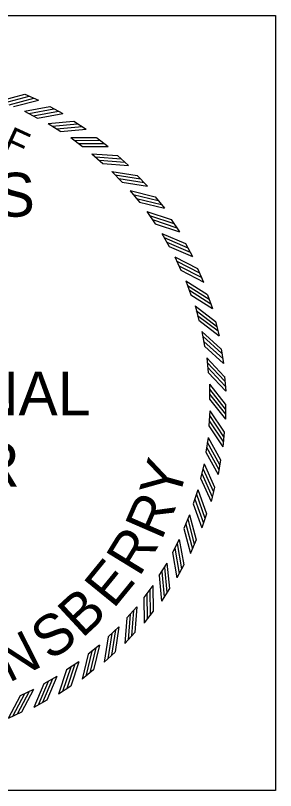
# Model space of a CAD drawing. Extents: x 166 to 3406, y 71 to 2074.
# Drawn here: x 3217.3 to 3309.8, y 386.2 to 662.3 of the extents above; entities that cross this region are included whole.
import ezdxf

# ---------------------------------------------------------------- set-up
doc = ezdxf.new("R2010")
doc.units = 0
doc.layers.add('R_No Plot', color=7, linetype='Continuous')
doc.layers.add('STAMP', color=7, linetype='Continuous')

msp = doc.modelspace()

# ---------------------------------------------------------------- linework, layer by layer
at = {"layer": 'R_No Plot'}
msp.add_lwpolyline([(3033.61, 662.33), (3309.76, 662.33), (3309.76, 386.19), (3033.61, 386.19)], close=True, dxfattribs=at)
at = {"layer": 'STAMP'}
for p, q in [((3220.55, 634.26), (3225.39, 632.19)), ((3229.45, 629.85), (3234.11, 627.38)), ((3220.47, 628.26), (3225.14, 625.78)), ((3237.96, 624.72), (3242.4, 621.88)), ((3228.88, 623.87), (3233.33, 621.02)), ((3236.9, 618.81), (3241.1, 615.6)), ((3246.02, 618.9), (3250.21, 615.7)), ((3244.47, 613.1), (3248.39, 609.56)), ((3253.57, 612.44), (3257.48, 608.91)), ((3251.55, 606.79), (3255.16, 602.94)), ((3260.56, 605.38), (3264.17, 601.53)), ((3258.08, 599.91), (3261.36, 595.77)), ((3266.94, 597.76), (3270.22, 593.63)), ((3264.02, 592.52), (3266.95, 588.13)), ((3272.68, 589.65), (3275.6, 585.26)), ((3269.33, 584.67), (3271.89, 580.04)), ((3277.72, 581.09), (3280.27, 576.47)), ((3273.97, 576.4), (3276.14, 571.58)), ((3282.04, 572.14), (3284.2, 567.33)), ((3277.92, 567.77), (3279.68, 562.79)), ((3285.6, 562.86), (3287.36, 557.89)), ((3281.14, 558.85), (3282.48, 553.74)), ((3288.39, 553.32), (3289.73, 548.22)), ((3283.61, 549.7), (3284.52, 544.49)), ((3290.38, 543.59), (3291.3, 538.39)), ((3285.31, 540.37), (3285.8, 535.11)), ((3291.56, 533.72), (3292.04, 528.47)), ((3286.24, 530.93), (3286.29, 525.65)), ((3291.92, 523.79), (3291.97, 518.52)), ((3286.39, 521.45), (3286, 516.18)), ((3291.46, 513.86), (3291.07, 508.6)), ((3285.76, 511.99), (3284.93, 506.77)), ((3284.34, 502.61), (3283.09, 497.47)), ((3290.18, 504.01), (3289.36, 498.8)), ((3282.16, 493.38), (3280.49, 488.37)), ((3288.09, 494.29), (3286.84, 489.17)), ((3279.22, 484.36), (3277.14, 479.51)), ((3285.2, 484.78), (3283.54, 479.78)), ((3275.54, 475.62), (3273.07, 470.95)), ((3281.55, 475.54), (3279.47, 470.7)), ((3271.16, 467.21), (3268.31, 462.76)), ((3277.14, 466.64), (3274.67, 461.98)), ((3266.1, 459.19), (3262.89, 454.99)), ((3272.01, 458.13), (3269.16, 453.69)), ((3260.39, 451.62), (3256.85, 447.7)), ((3266.19, 450.07), (3262.99, 445.88)), ((3254.08, 444.54), (3250.22, 440.93)), ((3259.73, 442.52), (3256.19, 438.61)), ((3247.2, 438.01), (3243.06, 434.73)), ((3252.67, 435.53), (3248.82, 431.92)), ((3239.81, 432.07), (3235.41, 429.14)), ((3245.05, 429.15), (3240.92, 425.87)), ((3231.95, 426.76), (3227.33, 424.2)), ((3236.93, 423.41), (3232.55, 420.49)), ((3223.68, 422.12), (3218.86, 419.95)), ((3228.37, 418.37), (3223.76, 415.82)), ((3219.42, 414.05), (3214.61, 411.89))]:
    msp.add_line(p, q, dxfattribs=at)
for points in [[(3211.72, 631.93), (3220.54, 634.26)], [(3213.27, 631.25), (3222.09, 633.58)], [(3214.97, 630.56), (3223.79, 632.89)], [(3216.58, 629.86), (3225.4, 632.19)], [(3220.46, 628.26), (3229.44, 629.85)], [(3221.95, 627.45), (3230.93, 629.04)], [(3223.59, 626.63), (3232.57, 628.22)], [(3225.13, 625.79), (3234.12, 627.38)], [(3228.87, 623.87), (3237.95, 624.72)], [(3230.29, 622.95), (3239.37, 623.79)], [(3231.85, 621.99), (3240.94, 622.84)], [(3233.32, 621.03), (3242.41, 621.88)], [(3236.89, 618.81), (3246.01, 618.9)], [(3238.23, 617.77), (3247.35, 617.86)], [(3239.71, 616.69), (3248.83, 616.78)], [(3241.09, 615.61), (3250.22, 615.7)], [(3244.46, 613.1), (3253.56, 612.44)], [(3245.71, 611.96), (3254.81, 611.29)], [(3247.1, 610.76), (3256.19, 610.1)], [(3248.39, 609.57), (3257.49, 608.91)], [(3251.54, 606.79), (3260.55, 605.38)], [(3252.69, 605.54), (3261.7, 604.13)], [(3253.97, 604.24), (3262.98, 602.83)], [(3255.16, 602.94), (3264.17, 601.53)], [(3258.07, 599.92), (3266.94, 597.77)], [(3259.11, 598.58), (3267.98, 596.43)], [(3260.28, 597.17), (3269.15, 595.02)], [(3261.36, 595.78), (3270.23, 593.63)], [(3264.01, 592.53), (3272.67, 589.65)], [(3264.94, 591.1), (3273.6, 588.23)], [(3265.99, 589.6), (3274.65, 586.73)], [(3266.95, 588.13), (3275.61, 585.26)], [(3269.32, 584.67), (3277.71, 581.09)], [(3270.13, 583.18), (3278.52, 579.6)], [(3271.05, 581.59), (3279.44, 578.01)], [(3271.89, 580.05), (3280.28, 576.47)], [(3273.96, 576.4), (3282.03, 572.14)], [(3274.65, 574.85), (3282.71, 570.59)], [(3275.43, 573.19), (3283.5, 568.93)], [(3276.14, 571.58), (3284.21, 567.33)], [(3277.91, 567.78), (3285.6, 562.87)], [(3278.46, 566.17), (3286.15, 561.26)], [(3279.11, 564.46), (3286.8, 559.55)], [(3279.68, 562.8), (3287.37, 557.89)], [(3281.13, 558.86), (3288.38, 553.33)], [(3281.55, 557.21), (3288.8, 551.68)], [(3282.05, 555.45), (3289.31, 549.92)], [(3282.48, 553.75), (3289.74, 548.22)], [(3283.6, 549.7), (3290.37, 543.59)], [(3283.88, 548.03), (3290.65, 541.92)], [(3284.24, 546.23), (3291.01, 540.12)], [(3284.53, 544.5), (3291.3, 538.39)], [(3285.31, 540.37), (3291.55, 533.73)], [(3285.45, 538.68), (3291.69, 532.03)], [(3285.66, 536.86), (3291.9, 530.22)], [(3285.8, 535.11), (3292.05, 528.46)], [(3286.24, 530.94), (3291.91, 523.8)], [(3286.24, 529.24), (3291.91, 522.1)], [(3286.3, 527.41), (3291.97, 520.27)], [(3286.3, 525.65), (3291.97, 518.51)], [(3286.25, 519.76), (3291.31, 512.18)], [(3286.39, 521.45), (3291.45, 513.87)], [(3286.15, 517.93), (3291.22, 510.35)], [(3286.01, 516.18), (3291.07, 508.6)], [(3285.75, 511.99), (3290.17, 504.02)], [(3285.23, 508.5), (3289.65, 500.53)], [(3285.47, 510.32), (3289.89, 502.34)], [(3284.94, 506.77), (3289.36, 498.79)], [(3284.34, 502.62), (3288.09, 494.3)], [(3283.92, 500.97), (3287.67, 492.66)], [(3283.1, 497.48), (3286.84, 489.16)], [(3283.53, 499.18), (3287.28, 490.87)], [(3281.6, 491.78), (3284.65, 483.19)], [(3282.15, 493.39), (3285.2, 484.79)], [(3281.06, 490.03), (3284.11, 481.44)], [(3280.49, 488.37), (3283.54, 479.78)], [(3279.21, 484.37), (3281.54, 475.55)], [(3277.85, 481.12), (3280.18, 472.3)], [(3278.53, 482.82), (3280.86, 474)], [(3277.14, 479.51), (3279.47, 470.69)], [(3275.54, 475.63), (3277.13, 466.65)], [(3273.91, 472.5), (3275.51, 463.52)], [(3274.73, 474.14), (3276.33, 465.16)], [(3273.08, 470.95), (3274.67, 461.97)], [(3271.16, 467.22), (3272.01, 458.14)], [(3269.28, 464.23), (3270.12, 455.15)], [(3270.23, 465.8), (3271.08, 456.72)], [(3268.32, 462.76), (3269.16, 453.68)], [(3266.1, 459.2), (3266.19, 450.08)], [(3263.98, 456.38), (3264.07, 447.26)], [(3265.06, 457.86), (3265.15, 448.74)], [(3262.9, 455), (3262.99, 445.87)], [(3259.24, 450.38), (3258.58, 441.28)], [(3260.39, 451.63), (3259.73, 442.53)], [(3256.85, 447.7), (3256.19, 438.6)], [(3258.04, 448.99), (3257.38, 439.9)], [(3251.52, 442.12), (3250.11, 433.11)], [(3252.83, 443.4), (3251.42, 434.39)], [(3254.08, 444.55), (3252.67, 435.54)], [(3250.23, 440.93), (3248.82, 431.92)], [(3245.86, 436.98), (3243.71, 428.11)], [(3247.2, 438.02), (3245.05, 429.15)], [(3243.07, 434.73), (3240.92, 425.86)], [(3244.45, 435.81), (3242.31, 426.94)], [(3238.39, 431.15), (3235.52, 422.49)], [(3239.81, 432.08), (3236.94, 423.42)], [(3235.42, 429.14), (3232.55, 420.48)], [(3236.89, 430.1), (3234.02, 421.44)], [(3230.46, 425.96), (3226.88, 417.57)], [(3231.95, 426.77), (3228.38, 418.38)], [(3227.34, 424.2), (3223.76, 415.81)], [(3228.88, 425.04), (3225.3, 416.65)], [(3218.87, 419.95), (3214.61, 411.88)], [(3220.48, 420.66), (3216.22, 412.59)], [(3222.13, 421.44), (3217.87, 413.38)], [(3223.69, 422.12), (3219.43, 414.06)]]:
    msp.add_lwpolyline(points, dxfattribs=at)

# ---------------------------------------------------------------- texts
for s, height, rotation, p in [('F', 9.59, 335.3628, (3212.1, 614.26)), ('Y', 14.57, 74.5264, (3275.17, 489.09)), ('R', 14.57, 66.5008, (3269.17, 475.04)), ('R', 14.57, 58.4752, (3261.26, 461.97)), ('E', 14.57, 50.8144, (3252.09, 450.63)), ('B', 14.57, 42.7888, (3240.94, 440.18)), ('S', 14.57, 35.4928, (3229.63, 432.12)), ('N', 14.57, 26.7376, (3214.85, 424.43))]:
    msp.add_text(s, height=height, rotation=rotation, dxfattribs=at).set_placement(p)
for s, height, p in [('ARKANSAS', 15.653, (3110.16, 590.66)), ('PROFESSIONAL', 15.6526, (3081.09, 519.82)), ('ENGINEER', 15.653, (3109.41, 494.48))]:
    msp.add_text(s, height=height, dxfattribs=at).set_placement(p)

doc.saveas('drawing.dxf')
